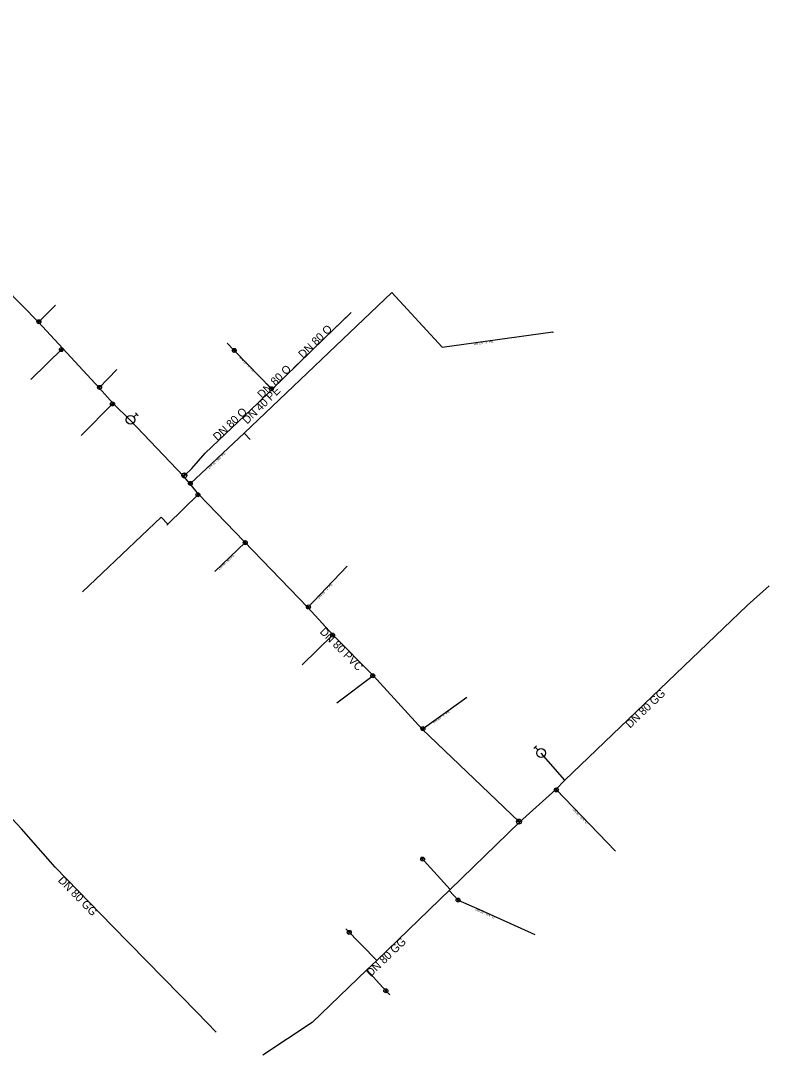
# Model space of a CAD drawing. Extents: x -446879 to -446633, y -1113504 to -1113264.
# Drawn here: x -446782.8 to -446632.9, y -1113504.4 to -1113297 of the extents above; entities that cross this region are included whole.
import ezdxf

# ---------------------------------------------------------------- set-up
doc = ezdxf.new("R2010")
doc.units = 0
for name, color, linetype in [('_hydrantova_odbocka_', 7, 'Continuous'), ('_pripojka_prevzato_z_dokumentace_', 7, 'Continuous'), ('_pripojka_priblizne_', 7, 'Continuous'), ('_voda_smvak_prevzato_z_dokumentace_', 7, 'Continuous'), ('_vodovodni_chranicka_', 7, 'Continuous'), ('Default', 7, 'Continuous'), ('MoLevel 27', 7, 'Continuous'), ('MoLevel 28', 7, 'Continuous'), ('MoLevel 32', 7, 'Continuous'), ('MoLevel 46', 7, 'Continuous'), ('MoLevel 53', 7, 'Continuous'), ('MoLevel 55', 7, 'Continuous'), ('MoLevel 60', 7, 'Continuous')]:
    doc.layers.add(name, color=color, linetype=linetype)

# ---------------------------------------------------------------- blocks, each defined once
blk = doc.blocks.new('_uzaver_')
at = {"layer": 'Default'}
for p, q in [((-0.000035, -0.000035), (0.000035, 0.000035)), ((0.000035, -0.000035), (-0.000035, 0.000035))]:
    blk.add_line(p, q, dxfattribs=at)
for radius in [0.00005, 0.0000025]:
    blk.add_circle((0, 0), radius, dxfattribs=at)
blk = doc.blocks.new('_uzaver_pripojka_')
at = {"layer": 'Default'}
for p, q in [((-0.000035, -0.000035), (0.000035, 0.000035)), ((0.000035, -0.000035), (-0.000035, 0.000035))]:
    blk.add_line(p, q, dxfattribs=at)
for radius in [0.00005, 0.0000025]:
    blk.add_circle((0, 0), radius, dxfattribs=at)
blk = doc.blocks.new('_hydrant_voda_')
at = {"layer": 'Default'}
for p, q in [((-0.000023, 0.000095), (0.000023, 0.000095)), ((0, 0.000095), (0, 0.00005))]:
    blk.add_line(p, q, dxfattribs=at)
blk.add_circle((0, 0), 0.00005, dxfattribs=at)

msp = doc.modelspace()

# ---------------------------------------------------------------- linework, layer by layer
at = {"layer": '_hydrantova_odbocka_'}
for p, q in [((-446760.89, -1113377.1), (-446760.82, -1113377.01)), ((-446673.81, -1113449.29), (-446678.58, -1113443.82))]:
    msp.add_line(p, q, dxfattribs=at)
at = {"layer": '_pripojka_prevzato_z_dokumentace_'}
for p, q in [((-446747.22, -1113391.95), (-446753.33, -1113397.97)), ((-446753.33, -1113397.97), (-446753.52, -1113398.16)), ((-446721.57, -1113410.72), (-446717.41, -1113406.35)), ((-446725.28, -1113414.62), (-446721.57, -1113410.72)), ((-446726.47, -1113426.11), (-446720.27, -1113420.12)), ((-446719.47, -1113433.74), (-446712.21, -1113428.27)), ((-446697.75, -1113435.7), (-446693.43, -1113432.6)), ((-446702.4, -1113439.03), (-446697.75, -1113435.7))]:
    msp.add_line(p, q, dxfattribs=at)
at = {"layer": '_pripojka_priblizne_'}
for p, q in [((-446779.26, -1113357.43), (-446775.82, -1113354.07)), ((-446780.81, -1113368.93), (-446774.41, -1113362.68)), ((-446767.09, -1113370.6), (-446763.56, -1113366.94)), ((-446770.69, -1113380.18), (-446764.34, -1113373.75)), ((-446738.04, -1113379.73), (-446736.88, -1113380.98)), ((-446737.85, -1113401.63), (-446743.96, -1113407.42)), ((-446675.59, -1113451.11), (-446663.68, -1113463.51)), ((-446696.76, -1113471.16), (-446702.67, -1113464.72)), ((-446690.94, -1113475.22), (-446679.8, -1113480.22)), ((-446711.51, -1113485.41), (-446717.67, -1113479.09))]:
    msp.add_line(p, q, dxfattribs=at)
for points in [[(-446738.04, -1113379.73), (-446708.51, -1113351.52), (-446698.38, -1113362.48), (-446676.23, -1113359.41), (-446676.14, -1113359.52)], [(-446732.51, -1113370.91), (-446732.61, -1113370.81), (-446740.04, -1113363.12), (-446741.43, -1113361.67)], [(-446748.88, -1113389.86), (-446748.81, -1113389.78), (-446738.04, -1113379.73)], [(-446753.33, -1113397.97), (-446754.7, -1113396.53), (-446770.42, -1113411.48)], [(-446696.96, -1113471.37), (-446695.2, -1113473.31), (-446690.94, -1113475.22)], [(-446713.46, -1113487.26), (-446709.68, -1113491.49), (-446708.89, -1113492.31)]]:
    msp.add_lwpolyline(points, dxfattribs=at)
at = {"layer": '_voda_smvak_prevzato_z_dokumentace_'}
for p, q in [((-446750.22, -1113388.31), (-446760.89, -1113377.1)), ((-446750.04, -1113388.16), (-446748.54, -1113386.75)), ((-446750.22, -1113388.31), (-446750.04, -1113388.16)), ((-446682.91, -1113457.7), (-446683.01, -1113457.57))]:
    msp.add_line(p, q, dxfattribs=at)
for points in [[(-446760.89, -1113377.1), (-446764.33, -1113373.76), (-446767.09, -1113370.6), (-446779.25, -1113357.44), (-446786.03, -1113350.55), (-446788.36, -1113348.05), (-446795.29, -1113340.78), (-446799.77, -1113335.76), (-446815.92, -1113318.89), (-446836.52, -1113297.01)], [(-446748.54, -1113386.75), (-446745.88, -1113383.7), (-446735.27, -1113373.61), (-446722.06, -1113360.7), (-446716.6, -1113355.49)], [(-446683.01, -1113457.57), (-446702.41, -1113439.02), (-446712.21, -1113428.27), (-446720.27, -1113420.12), (-446725.28, -1113414.62), (-446747.22, -1113391.95), (-446748.88, -1113389.86), (-446750.22, -1113388.31)], [(-446632.87, -1113410.29), (-446637.32, -1113414.23), (-446673.81, -1113449.29)], [(-446743.69, -1113499.76), (-446747.47, -1113495.83), (-446764.41, -1113478.5), (-446775.92, -1113466.68), (-446782.64, -1113459.03), (-446791.63, -1113449.52), (-446798.08, -1113442.84), (-446807.86, -1113431.13)], [(-446673.81, -1113449.29), (-446675.63, -1113451.14), (-446682.91, -1113457.7)], [(-446682.91, -1113457.7), (-446696.76, -1113471.16), (-446711.51, -1113485.41), (-446713.46, -1113487.26), (-446724.46, -1113497.86), (-446734.31, -1113504.42)]]:
    msp.add_lwpolyline(points, dxfattribs=at)
at = {"layer": '_vodovodni_chranicka_'}
msp.add_line((-446732.25, -1113370.66), (-446728.78, -1113367.26), dxfattribs=at)
for points in [[(-446728.24, -1113366.74), (-446722.06, -1113360.7), (-446716.93, -1113355.81)], [(-446746.44, -1113384.34), (-446745.88, -1113383.7), (-446735.27, -1113373.61), (-446732.8, -1113371.19)]]:
    msp.add_lwpolyline(points, dxfattribs=at)

# ---------------------------------------------------------------- block references
at = {"layer": 'MoLevel 27', "xscale": 10000, "yscale": 10000}
for p, rotation in [((-446750.04, -1113388.16), 41.6487657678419), ((-446683.01, -1113457.57), 136.27603866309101)]:
    msp.add_blockref('_uzaver_', p, dxfattribs=dict(at, rotation=rotation))
at = {"layer": 'MoLevel 28', "yscale": 17636.684303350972}
for p, xscale, rotation in [((-446760.82, -1113377.01), 17636.684303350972, -48.41102875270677), ((-446678.58, -1113443.82), 17636.68430335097, 45.10981448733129)]:
    msp.add_blockref('_hydrant_voda_', p, dxfattribs=dict(at, xscale=xscale, rotation=rotation))
at = {"layer": 'MoLevel 53'}
for p, xscale, yscale, rotation in [((-446779.18, -1113357.36), 8000, 8000, 44.375430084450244), ((-446774.66, -1113362.93), 7999.999999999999, 7999.999999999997, -135.66877604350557), ((-446740.04, -1113363.12), 7999.999999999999, 7999.999999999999, 134.7407448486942), ((-446767.02, -1113370.52), 8000, 8000.000000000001, 46.48471978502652), ((-446732.61, -1113370.81), 7999.999999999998, 8000, 134.003401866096), ((-446764.43, -1113373.83), 7999.999999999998, 8000, -134.57265376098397), ((-446748.81, -1113389.78), 7999.999999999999, 8000.000000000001, 43.021634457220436), ((-446737.85, -1113401.63), 7999.999999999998, 8000, -138.45331625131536), ((-446675.52, -1113451.21), 7999.999999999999, 7999.999999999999, -45.86287587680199)]:
    msp.add_blockref('_uzaver_pripojka_', p, dxfattribs=dict(at, xscale=xscale, yscale=yscale, rotation=rotation))
at = {"layer": 'MoLevel 53', "xscale": 7999.999999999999, "yscale": 7999.999999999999}
for p in [(-446747.33, -1113392.05), (-446725.2, -1113414.54), (-446720.35, -1113420.19), (-446712.3, -1113428.33), (-446702.26, -1113438.93), (-446702.33, -1113465.09), (-446695.2, -1113473.31), (-446717, -1113479.77), (-446709.68, -1113491.49)]:
    msp.add_blockref('_uzaver_pripojka_', p, dxfattribs=at)

# ---------------------------------------------------------------- texts
at = {"layer": 'MoLevel 32'}
for s, rotation, p in [("DN 25 - 1'' PE", 7.898, (-446692.05, -1113362.06)), ("DN 25 - 1'' PE", 314.0079, (-446739.06, -1113364.59)), ("DN 32 - 5/4'' PE", 43.0215, (-446745.01, -1113386.86)), ('DN 40 - 6/4 PE', 43.4899, (-446743.02, -1113407.15)), ("DN 32 - 5/4'' O", 313.8462, (-446672.34, -1113455.15)), ("DN 32 - 5/4'' O", 335.8246, (-446691.79, -1113475.34))]:
    msp.add_text(s, height=0.455, rotation=rotation, dxfattribs=at).set_placement(p)
at = {"layer": 'MoLevel 46'}
for s, rotation, p in [('DN 40 PE', 44.3507, (-446737.46, -1113377.99)), ('DN 80 PVC', 314.6819, (-446723.03, -1113419.61)), ('DN 80 GG', 43.855, (-446660.75, -1113438.96)), ('DN 80 GG', 314.2387, (-446775.46, -1113469.45)), ('DN 80 GG', 44.0122, (-446712.68, -1113488.77))]:
    msp.add_text(s, height=1.605, rotation=rotation, dxfattribs=at).set_placement(p)
at = {"layer": 'MoLevel 55'}
for rotation, p in [(46.4479, (-446723.04, -1113412.93)), (35.6174, (-446700.04, -1113437.9))]:
    msp.add_text("DN 25 - 1'' PE", height=0.455, rotation=rotation, dxfattribs=at).set_placement(p)
at = {"layer": 'MoLevel 60'}
for rotation, p in [(44.3507, (-446726.26, -1113364.8)), (44.3507, (-446734.47, -1113372.83)), (43.5667, (-446743.39, -1113381.33))]:
    msp.add_text('DN 80 O', height=1.605, rotation=rotation, dxfattribs=at).set_placement(p)

doc.saveas('drawing.dxf')
